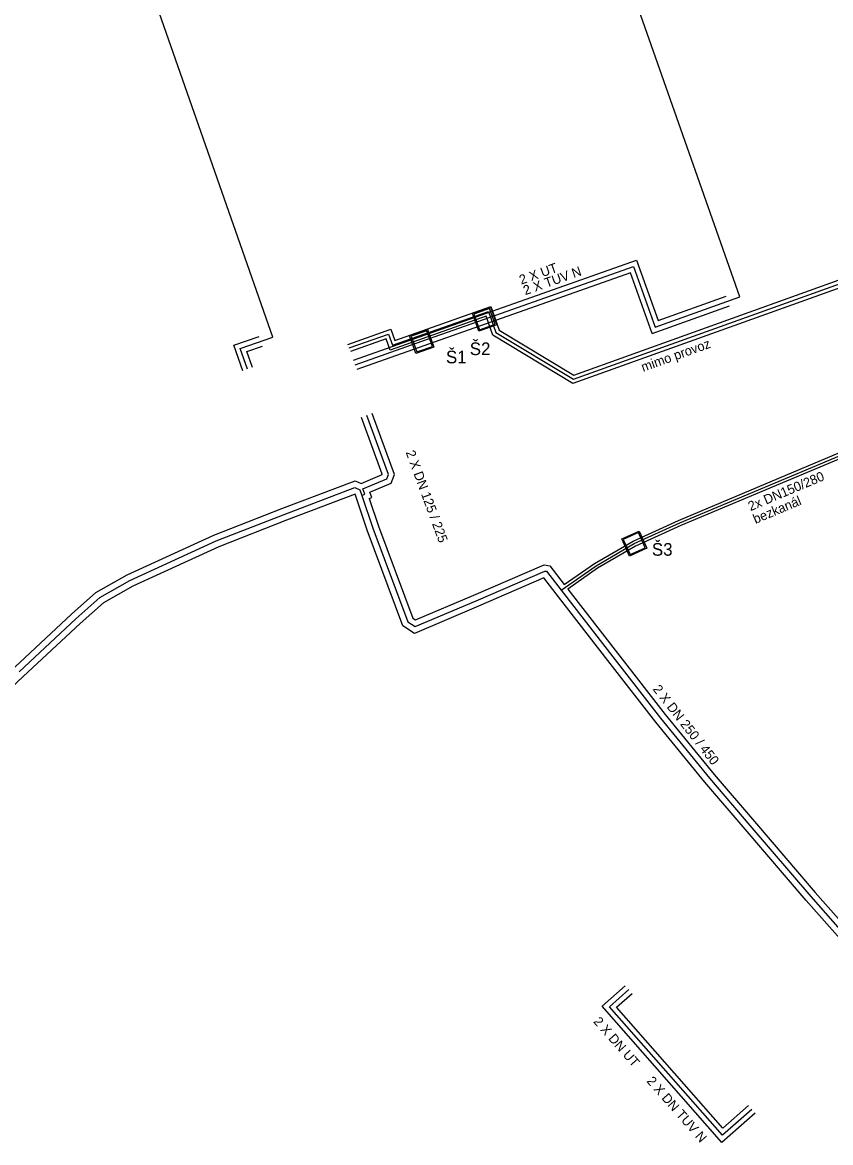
# Model space of a CAD drawing. Extents: x -606118 to -604472, y -1157869 to -1156854.
# Drawn here: x -605482 to -605354.3, y -1157643.2 to -1157466.1 of the extents above; entities that cross this region are included whole.
import ezdxf

# ---------------------------------------------------------------- set-up
doc = ezdxf.new("R2010")
doc.units = 0
for name, color, linetype in [('Osa trasy teplovodu', 7, 'Continuous'), ('označení šachty', 7, 'Continuous'), ('Teplovod - trasa - okraj', 7, 'Continuous'), ('Teplovod - trasa popis', 7, 'Continuous'), ('Teplovod - trasa popis 2', 7, 'Continuous'), ('Šachta trasy teplovodu', 7, 'Continuous')]:
    doc.layers.add(name, color=color, linetype=linetype)

msp = doc.modelspace()

# ---------------------------------------------------------------- linework, layer by layer
at = {"layer": 'Osa trasy teplovodu'}
for p, q in [((-605368.63, -1157509.48), (-605387.36, -1157456.17)), ((-605442.45, -1157515.86), (-605461.13, -1157462.51)), ((-605381.99, -1157514.28), (-605368.63, -1157509.48))]:
    msp.add_line(p, q, dxfattribs=at)
for points in [[(-605385.3, -1157548.52), (-605378.11, -1157545.25), (-605355.5, -1157535.73), (-605332.89, -1157526.22), (-605335.29, -1157508.13), (-605337.6, -1157494.53)], [(-605429.43, -1157520.25), (-605418.9, -1157516.53), (-605418.9, -1157516.53), (-605408.97, -1157513.02), (-605385.43, -1157504.7), (-605381.99, -1157514.28)], [(-605430.37, -1157517.58), (-605424.17, -1157515.39), (-605423.54, -1157517.15), (-605408.37, -1157511.79), (-605407.18, -1157515.16), (-605394.93, -1157522.53), (-605350.67, -1157506.64)], [(-605446.45, -1157520.95), (-605447.6, -1157517.65), (-605442.45, -1157515.86)], [(-605428.36, -1157540.9), (-605427.92, -1157540.71), (-605428.21, -1157539.87), (-605424.45, -1157538.26), (-605424.17, -1157537.58), (-605427.59, -1157528.27)], [(-605482.58, -1157568.8), (-605473.59, -1157560.43), (-605469.82, -1157557.04), (-605465.04, -1157554.33), (-605451.39, -1157548.09), (-605440.66, -1157543.89), (-605429.48, -1157539.67), (-605428.71, -1157540), (-605428.36, -1157540.9)], [(-605428.36, -1157540.9), (-605426.64, -1157546.09), (-605421.1, -1157560.91), (-605419.96, -1157561.64), (-605410.31, -1157557.54), (-605399.42, -1157552.85), (-605399.2, -1157552.89), (-605396.88, -1157555.9)], [(-605396.88, -1157555.9), (-605391.35, -1157552.03), (-605385.3, -1157548.52)], [(-605396.88, -1157555.9), (-605388.35, -1157566.92), (-605381.14, -1157576.13), (-605373.4, -1157585.62), (-605367.05, -1157593.07), (-605357.39, -1157604.32), (-605349.62, -1157613.1), (-605343.11, -1157620.55), (-605334.92, -1157629.93), (-605333.99, -1157630.97)], [(-605366.74, -1157637.99), (-605371.37, -1157642.08), (-605389.24, -1157621.75), (-605386.19, -1157619.05)]]:
    msp.add_lwpolyline(points, dxfattribs=at)
at = {"layer": 'Teplovod - trasa - okraj'}
for p, q in [((-605368.63, -1157509.48), (-605387.36, -1157456.17)), ((-605442.45, -1157515.86), (-605461.13, -1157462.51)), ((-605381.51, -1157513.26), (-605370.78, -1157509.41)), ((-605382.47, -1157515.3), (-605370.27, -1157510.92))]:
    msp.add_line(p, q, dxfattribs=at)
for points in [[(-605385.5, -1157548.12), (-605378.29, -1157544.84), (-605355.68, -1157535.32), (-605333.39, -1157525.93), (-605335.74, -1157508.2), (-605338.04, -1157494.61)], [(-605337.15, -1157494.46), (-605334.84, -1157508.07), (-605332.4, -1157526.5), (-605355.33, -1157536.15), (-605377.93, -1157545.66), (-605385.09, -1157548.92)], [(-605429.69, -1157519.49), (-605384.94, -1157503.68), (-605381.51, -1157513.26)], [(-605430.57, -1157517.01), (-605423.8, -1157514.62), (-605423.18, -1157516.39), (-605408.01, -1157511.03), (-605406.69, -1157514.76), (-605394.87, -1157521.87), (-605350.87, -1157506.08)], [(-605382.47, -1157515.3), (-605385.91, -1157505.72), (-605429.16, -1157521)], [(-605350.46, -1157507.21), (-605395, -1157523.2), (-605407.68, -1157515.56), (-605408.74, -1157512.56), (-605423.91, -1157517.92), (-605424.53, -1157516.15), (-605430.17, -1157518.14)], [(-605447.21, -1157521.21), (-605448.62, -1157517.15), (-605444.62, -1157515.76)], [(-605445.69, -1157520.69), (-605446.58, -1157518.14), (-605444.08, -1157517.27)], [(-605428.48, -1157539.01), (-605425.14, -1157537.58), (-605425.14, -1157537.56), (-605428.44, -1157528.58)], [(-605427.2, -1157541.37), (-605426.81, -1157541.2), (-605427.09, -1157540.37), (-605423.75, -1157538.94), (-605423.21, -1157537.59), (-605426.75, -1157527.96)], [(-605483.26, -1157568.07), (-605474.27, -1157559.69), (-605470.41, -1157556.23), (-605465.49, -1157553.43), (-605451.78, -1157547.16), (-605441.02, -1157542.96), (-605429.45, -1157538.59), (-605428.48, -1157539.01)], [(-605429.42, -1157540.71), (-605440.3, -1157544.82), (-605451, -1157549.01), (-605464.58, -1157555.22), (-605469.23, -1157557.86), (-605472.92, -1157561.17), (-605481.9, -1157569.53), (-605490.28, -1157577.38)], [(-605397.63, -1157556.48), (-605399.58, -1157553.95), (-605409.93, -1157558.42), (-605420.05, -1157562.71), (-605421.88, -1157561.53), (-605427.54, -1157546.41), (-605429.42, -1157540.71)], [(-605427.2, -1157541.37), (-605425.75, -1157545.78), (-605420.32, -1157560.28), (-605419.87, -1157560.57), (-605410.68, -1157556.67), (-605399.53, -1157551.87), (-605398.67, -1157552.03), (-605396.38, -1157554.99)], [(-605396.38, -1157554.99), (-605391.6, -1157551.65), (-605385.5, -1157548.12)], [(-605385.09, -1157548.92), (-605391.11, -1157552.4), (-605395.83, -1157555.71)], [(-605395.83, -1157555.71), (-605387.6, -1157566.34), (-605380.4, -1157575.54), (-605372.67, -1157585.01), (-605366.32, -1157592.45), (-605356.68, -1157603.7), (-605348.91, -1157612.48), (-605342.4, -1157619.93), (-605334.21, -1157629.3), (-605333.28, -1157630.33)], [(-605335.24, -1157630.99), (-605335.63, -1157630.56), (-605343.83, -1157621.18), (-605350.34, -1157613.73), (-605358.11, -1157604.95), (-605367.77, -1157593.69), (-605374.13, -1157586.23), (-605381.88, -1157576.73), (-605389.1, -1157567.5), (-605397.63, -1157556.48)], [(-605366.21, -1157638.58), (-605371.44, -1157643.21), (-605390.37, -1157621.68), (-605386.72, -1157618.46)], [(-605367.27, -1157637.39), (-605371.3, -1157640.95), (-605388.12, -1157621.82), (-605385.66, -1157619.65)]]:
    msp.add_lwpolyline(points, dxfattribs=at)
at = {"layer": 'Šachta trasy teplovodu'}
for points in [[(-605409.89, -1157514.94), (-605410.89, -1157512.1), (-605408.06, -1157511.1), (-605407.05, -1157513.93), (-605409.89, -1157514.94)], [(-605407.29, -1157513.82), (-605408.17, -1157511.34), (-605410.65, -1157512.22), (-605409.77, -1157514.7), (-605407.29, -1157513.82)], [(-605419.82, -1157518.45), (-605420.82, -1157515.61), (-605417.99, -1157514.61), (-605416.98, -1157517.44), (-605419.82, -1157518.45)], [(-605417.22, -1157517.33), (-605418.1, -1157514.85), (-605420.58, -1157515.73), (-605419.7, -1157518.21), (-605417.22, -1157517.33)], [(-605386.04, -1157550.51), (-605387.29, -1157547.77), (-605384.55, -1157546.53), (-605383.31, -1157549.26), (-605386.04, -1157550.51)], [(-605383.56, -1157549.17), (-605384.65, -1157546.77), (-605387.04, -1157547.86), (-605385.95, -1157550.26), (-605383.56, -1157549.17)]]:
    msp.add_lwpolyline(points, dxfattribs=at)

# ---------------------------------------------------------------- texts
at = {"layer": 'označení šachty'}
for s, p in [('Š2', (-605411.32, -1157518.71)), ('Š1', (-605415.08, -1157520.01)), ('Š3', (-605382.52, -1157550.43))]:
    msp.add_text(s, height=2, dxfattribs=at).set_placement(p)
at = {"layer": 'Teplovod - trasa popis'}
for s, rotation, p in [('2 X UT', 19.4806, (-605403.18, -1157507.58)), ('2 X DN 125 / 225', 290.2031, (-605421.46, -1157534.08)), ('2x DN150/280', 22.8286, (-605366.93, -1157543.4)), ('2 X DN 250 / 450', 308.0794, (-605382.45, -1157571.56)), ('2 X DN UT', 311.3453, (-605391.86, -1157624.15))]:
    msp.add_text(s, height=1.5, rotation=rotation, dxfattribs=at).set_placement(p)
at = {"layer": 'Teplovod - trasa popis 2'}
for s, rotation, p in [('2 X TUV N', 19.4806, (-605402.55, -1157509.25)), ('mimo provoz', 19.7473, (-605383.9, -1157521.37)), ('bezkanál', 22.8286, (-605366.15, -1157545.41)), ('2 X DN TUV N', 311.3453, (-605383.44, -1157633.57))]:
    msp.add_text(s, height=1.5, rotation=rotation, dxfattribs=at).set_placement(p)

doc.saveas('drawing.dxf')
